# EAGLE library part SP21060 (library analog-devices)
ANALOG DEVICES
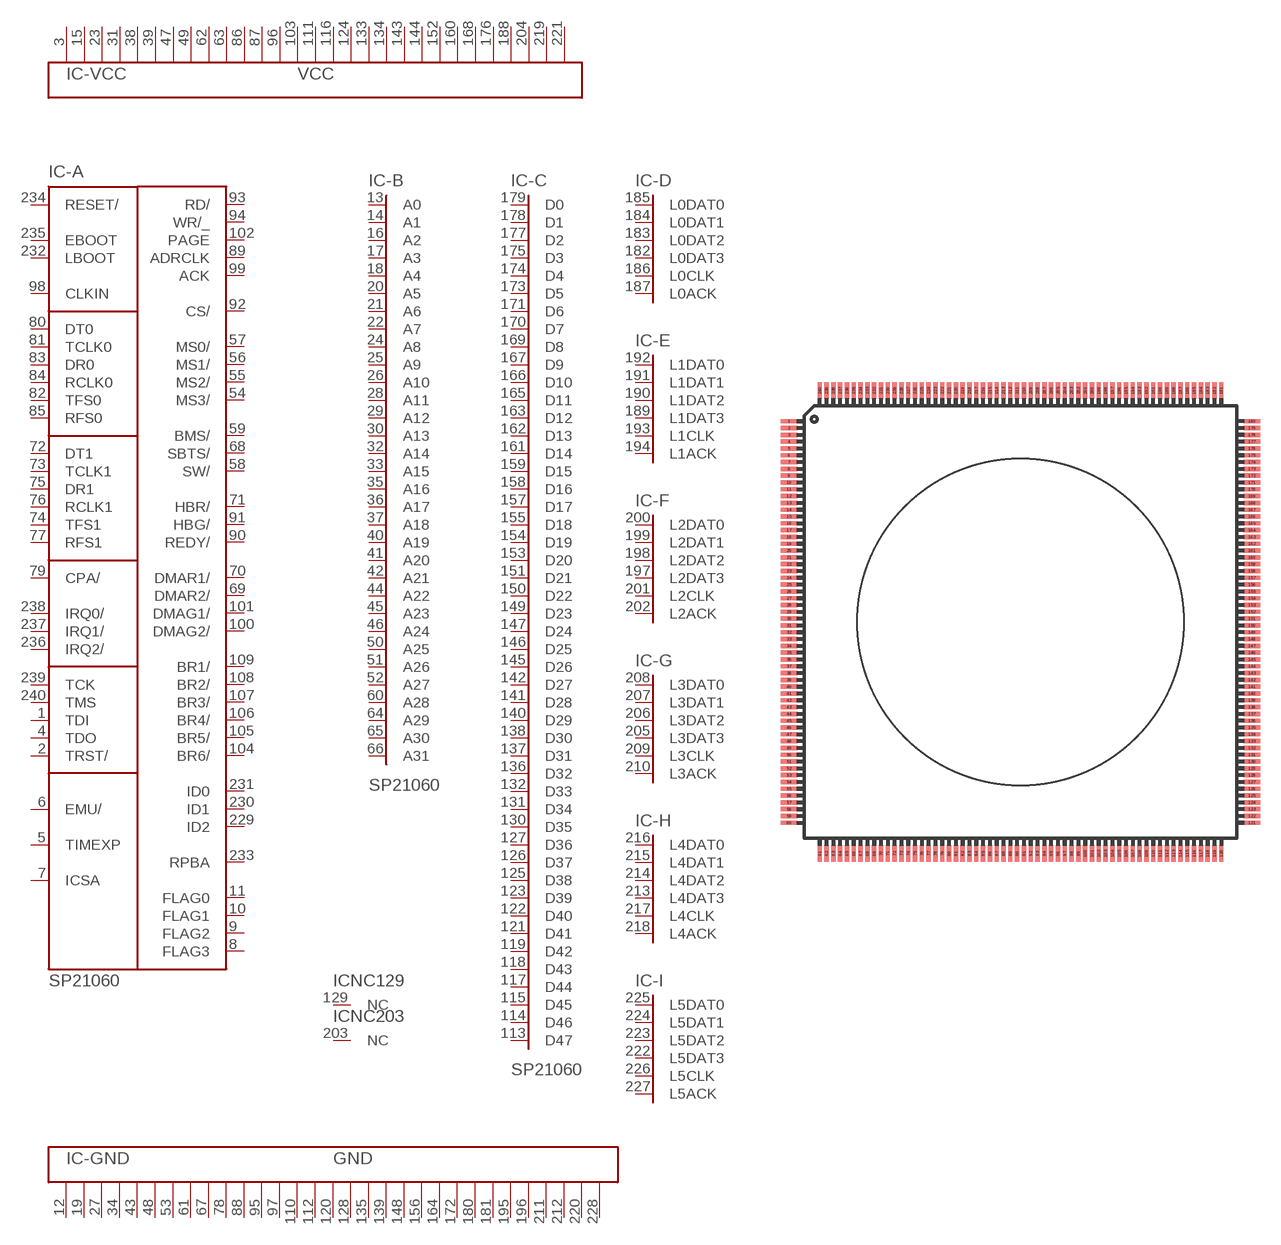
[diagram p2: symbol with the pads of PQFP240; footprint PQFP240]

Designator prefix IC; gates -A=SP21060C -B=A31 -C=D47 -D=L0 -E=L1 -F=L2 -G=L3 -H=L4 -I=L5 -VCC=VCC29 -GND=GND31 NC129=NC NC203=NC

## SP21060 (MPN: ADSP-21060KSZ-133; OC_FARNELL: 1438767; OC_NEWARK: 46M5216)  [PQFP240]
1  -A:TDI  in
2  -A:TRST/  in
3  -VCC:VCC  pwr
4  -A:TDO  out
5  -A:TIMEXP  out
6  -A:EMU/  out
7  -A:ICSA  out
8  -A:FLAG3
9  -A:FLAG2
10  -A:FLAG1
11  -A:FLAG0
12  -GND:GND  pwr
13  -B:A0
14  -B:A1
15  -VCC:VCC  pwr
16  -B:A2
17  -B:A3
18  -B:A4
19  -GND:GND  pwr
20  -B:A5
21  -B:A6
22  -B:A7
23  -VCC:VCC  pwr
24  -B:A8
25  -B:A9
26  -B:A10
27  -GND:GND  pwr
28  -B:A11
29  -B:A12
30  -B:A13
31  -VCC:VCC  pwr
32  -B:A14
33  -B:A15
34  -GND:GND  pwr
35  -B:A16
36  -B:A17
37  -B:A18
38  -VCC:VCC  pwr
39  -VCC:VCC  pwr
40  -B:A19
41  -B:A20
42  -B:A21
43  -GND:GND  pwr
44  -B:A22
45  -B:A23
46  -B:A24
47  -VCC:VCC  pwr
48  -GND:GND  pwr
49  -VCC:VCC  pwr
50  -B:A25
51  -B:A26
52  -B:A27
53  -GND:GND  pwr
54  -A:MS3/  hiz
55  -A:MS2/  hiz
56  -A:MS1/  hiz
57  -A:MS0/  hiz
58  -A:SW/  hiz
59  -A:BMS/
60  -B:A28
61  -GND:GND  pwr
62  -VCC:VCC  pwr
63  -VCC:VCC  pwr
64  -B:A29
65  -B:A30
66  -B:A31
67  -GND:GND  pwr
68  -A:SBTS/  in
69  -A:DMAR2/  in
70  -A:DMAR1/  in
71  -A:HBR/  in
72  -A:DT1  out
73  -A:TCLK1
74  -A:TFS1
75  -A:DR1  in
76  -A:RCLK1
77  -A:RFS1
78  -GND:GND  pwr
79  -A:CPA/
80  -A:DT0  out
81  -A:TCLK0
82  -A:TFS0
83  -A:DR0  in
84  -A:RCLK0
85  -A:RFS0
86  -VCC:VCC  pwr
87  -VCC:VCC  pwr
88  -GND:GND  pwr
89  -A:ADRCLK  hiz
90  -A:REDY/  out
91  -A:HBG/
92  -A:CS/  in
93  -A:RD/  hiz
94  -A:WR/_  hiz
95  -GND:GND  pwr
96  -VCC:VCC  pwr
97  -GND:GND  pwr
98  -A:CLKIN  in
99  -A:ACK
100  -A:DMAG2/  hiz
101  -A:DMAG1/  hiz
102  -A:PAGE  hiz
103  -VCC:VCC  pwr
104  -A:BR6/
105  -A:BR5/
106  -A:BR4/
107  -A:BR3/
108  -A:BR2/
109  -A:BR1/
110  -GND:GND  pwr
111  -VCC:VCC  pwr
112  -GND:GND  pwr
113  -C:D47
114  -C:D46
115  -C:D45
116  -VCC:VCC  pwr
117  -C:D44
118  -C:D43
119  -C:D42
120  -GND:GND  pwr
121  -C:D41
122  -C:D40
123  -C:D39
124  -VCC:VCC  pwr
125  -C:D38
126  -C:D37
127  -C:D36
128  -GND:GND  pwr
129  NC129:NC  nc
130  -C:D35
131  -C:D34
132  -C:D33
133  -VCC:VCC  pwr
134  -VCC:VCC  pwr
135  -GND:GND  pwr
136  -C:D32
137  -C:D31
138  -C:D30
139  -GND:GND  pwr
140  -C:D29
141  -C:D28
142  -C:D27
143  -VCC:VCC  pwr
144  -VCC:VCC  pwr
145  -C:D26
146  -C:D25
147  -C:D24
148  -GND:GND  pwr
149  -C:D23
150  -C:D22
151  -C:D21
152  -VCC:VCC  pwr
153  -C:D20
154  -C:D19
155  -C:D18
156  -GND:GND  pwr
157  -C:D17
158  -C:D16
159  -C:D15
160  -VCC:VCC  pwr
161  -C:D14
162  -C:D13
163  -C:D12
164  -GND:GND  pwr
165  -C:D11
166  -C:D10
167  -C:D9
168  -VCC:VCC  pwr
169  -C:D8
170  -C:D7
171  -C:D6
172  -GND:GND  pwr
173  -C:D5
174  -C:D4
175  -C:D3
176  -VCC:VCC  pwr
177  -C:D2
178  -C:D1
179  -C:D0
180  -GND:GND  pwr
181  -GND:GND  pwr
182  -D:L0DAT3
183  -D:L0DAT2
184  -D:L0DAT1
185  -D:L0DAT0
186  -D:L0CLK
187  -D:L0ACK
188  -VCC:VCC  pwr
189  -E:L1DAT3
190  -E:L1DAT2
191  -E:L1DAT1
192  -E:L1DAT0
193  -E:L1CLK
194  -E:L1ACK
195  -GND:GND  pwr
196  -GND:GND  pwr
197  -F:L2DAT3
198  -F:L2DAT2
199  -F:L2DAT1
200  -F:L2DAT0
201  -F:L2CLK
202  -F:L2ACK
203  NC203:NC  nc
204  -VCC:VCC  pwr
205  -G:L3DAT3
206  -G:L3DAT2
207  -G:L3DAT1
208  -G:L3DAT0
209  -G:L3CLK
210  -G:L3ACK
211  -GND:GND  pwr
212  -GND:GND  pwr
213  -H:L4DAT3
214  -H:L4DAT2
215  -H:L4DAT1
216  -H:L4DAT0
217  -H:L4CLK
218  -H:L4ACK
219  -VCC:VCC  pwr
220  -GND:GND  pwr
221  -VCC:VCC  pwr
222  -I:L5DAT3
223  -I:L5DAT2
224  -I:L5DAT1
225  -I:L5DAT0
226  -I:L5CLK
227  -I:L5ACK
228  -GND:GND  pwr
229  -A:ID2  in
230  -A:ID1  in
231  -A:ID0  in
232  -A:LBOOT  in
233  -A:RPBA  in
234  -A:RESET/  in
235  -A:EBOOT  in
236  -A:IRQ2/  in
237  -A:IRQ1/  in
238  -A:IRQ0/  in
239  -A:TCK  in
240  -A:TMS  in

## Footprint PQFP240 (pad centres in mm)
PLASTIC QUAD FLAT PACK
smd 1.2 x 0.32: 1 -17,14.75; 2 -17,14.25; 3 -17,13.75; 4 -17,13.25; 5 -17,12.75; 6 -17,12.25; 7 -17,11.75; 8 -17,11.25; 9 -17,10.75; 10 -17,10.25; 11 -17,9.75; 12 -17,9.25; 13 -17,8.75; 14 -17,8.25; 15 -17,7.75; 16 -17,7.25; 17 -17,6.75; 18 -17,6.25; 19 -17,5.75; 20 -17,5.25; 21 -17,4.75; 22 -17,4.25; 23 -17,3.75; 24 -17,3.25; 25 -17,2.75; 26 -17,2.25; 27 -17,1.75; 28 -17,1.25; 29 -17,0.75; 30 -17,0.25; 31 -17,-0.25; 32 -17,-0.75; 33 -17,-1.25; 34 -17,-1.75; 35 -17,-2.25; 36 -17,-2.75; 37 -17,-3.25; 38 -17,-3.75; 39 -17,-4.25; 40 -17,-4.75; 41 -17,-5.25; 42 -17,-5.75; 43 -17,-6.25; 44 -17,-6.75; 45 -17,-7.25; 46 -17,-7.75; 47 -17,-8.25; 48 -17,-8.75; 49 -17,-9.25; 50 -17,-9.75; 51 -17,-10.25; 52 -17,-10.75; 53 -17,-11.25; 54 -17,-11.75; 55 -17,-12.25; 56 -17,-12.75; 57 -17,-13.25; 58 -17,-13.75; 59 -17,-14.25; 60 -17,-14.75; 121 17,-14.75; 122 17,-14.25; 123 17,-13.75; 124 17,-13.25; 125 17,-12.75; 126 17,-12.25; 127 17,-11.75; 128 17,-11.25; 129 17,-10.75; 130 17,-10.25; 131 17,-9.75; 132 17,-9.25; 133 17,-8.75; 134 17,-8.25; 135 17,-7.75; 136 17,-7.25; 137 17,-6.75; 138 17,-6.25; 139 17,-5.75; 140 17,-5.25; 141 17,-4.75; 142 17,-4.25; 143 17,-3.75; 144 17,-3.25; 145 17,-2.75; 146 17,-2.25; 147 17,-1.75; 148 17,-1.25; 149 17,-0.75; 150 17,-0.25; 151 17,0.25; 152 17,0.75; 153 17,1.25; 154 17,1.75; 155 17,2.25; 156 17,2.75; 157 17,3.25; 158 17,3.75; 159 17,4.25; 160 17,4.75; 161 17,5.25; 162 17,5.75; 163 17,6.25; 164 17,6.75; 165 17,7.25; 166 17,7.75; 167 17,8.25; 168 17,8.75; 169 17,9.25; 170 17,9.75; 171 17,10.25; 172 17,10.75; 173 17,11.25; 174 17,11.75; 175 17,12.25; 176 17,12.75; 177 17,13.25; 178 17,13.75; 179 17,14.25; 180 17,14.75
smd 0.32 x 1.2: 61 -14.75,-17; 62 -14.25,-17; 63 -13.75,-17; 64 -13.25,-17; 65 -12.75,-17; 66 -12.25,-17; 67 -11.75,-17; 68 -11.25,-17; 69 -10.75,-17; 70 -10.25,-17; 71 -9.75,-17; 72 -9.25,-17; 73 -8.75,-17; 74 -8.25,-17; 75 -7.75,-17; 76 -7.25,-17; 77 -6.75,-17; 78 -6.25,-17; 79 -5.75,-17; 80 -5.25,-17; 81 -4.75,-17; 82 -4.25,-17; 83 -3.75,-17; 84 -3.25,-17; 85 -2.75,-17; 86 -2.25,-17; 87 -1.75,-17; 88 -1.25,-17; 89 -0.75,-17; 90 -0.25,-17; 91 0.25,-17; 92 0.75,-17; 93 1.25,-17; 94 1.75,-17; 95 2.25,-17; 96 2.75,-17; 97 3.25,-17; 98 3.75,-17; 99 4.25,-17; 100 4.75,-17; 101 5.25,-17; 102 5.75,-17; 103 6.25,-17; 104 6.75,-17; 105 7.25,-17; 106 7.75,-17; 107 8.25,-17; 108 8.75,-17; 109 9.25,-17; 110 9.75,-17; 111 10.25,-17; 112 10.75,-17; 113 11.25,-17; 114 11.75,-17; 115 12.25,-17; 116 12.75,-17; 117 13.25,-17; 118 13.75,-17; 119 14.25,-17; 120 14.75,-17; 181 14.75,17; 182 14.25,17; 183 13.75,17; 184 13.25,17; 185 12.75,17; 186 12.25,17; 187 11.75,17; 188 11.25,17; 189 10.75,17; 190 10.25,17; 191 9.75,17; 192 9.25,17; 193 8.75,17; 194 8.25,17; 195 7.75,17; 196 7.25,17; 197 6.75,17; 198 6.25,17; 199 5.75,17; 200 5.25,17; 201 4.75,17; 202 4.25,17; 203 3.75,17; 204 3.25,17; 205 2.75,17; 206 2.25,17; 207 1.75,17; 208 1.25,17; 209 0.75,17; 210 0.25,17; 211 -0.25,17; 212 -0.75,17; 213 -1.25,17; 214 -1.75,17; 215 -2.25,17; 216 -2.75,17; 217 -3.25,17; 218 -3.75,17; 219 -4.25,17; 220 -4.75,17; 221 -5.25,17; 222 -5.75,17; 223 -6.25,17; 224 -6.75,17; 225 -7.25,17; 226 -7.75,17; 227 -8.25,17; 228 -8.75,17; 229 -9.25,17; 230 -9.75,17; 231 -10.25,17; 232 -10.75,17; 233 -11.25,17; 234 -11.75,17; 235 -12.25,17; 236 -12.75,17; 237 -13.25,17; 238 -13.75,17; 239 -14.25,17; 240 -14.75,17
